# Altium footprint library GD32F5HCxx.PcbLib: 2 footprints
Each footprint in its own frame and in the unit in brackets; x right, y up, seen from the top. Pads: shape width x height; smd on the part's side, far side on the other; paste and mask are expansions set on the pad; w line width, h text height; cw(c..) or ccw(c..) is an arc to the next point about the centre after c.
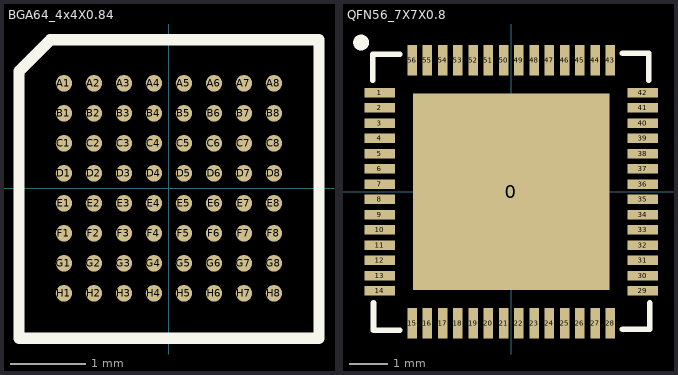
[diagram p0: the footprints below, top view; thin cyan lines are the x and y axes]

## BGA64_4x4X0.84 [mm]
pads (64):
  round 0.22 smd mask+0.05: A1(-1.4,1.4) A2(-1,1.4) A3(-0.6,1.4) A4(-0.2,1.4) A5(0.2,1.4) A6(0.6,1.4) A7(1,1.4) A8(1.4,1.4) B1(-1.4,1) B2(-1,1) B3(-0.6,1) B4(-0.2,1) B5(0.2,1) B6(0.6,1) B7(1,1) B8(1.4,1) C1(-1.4,0.6) C2(-1,0.6) C3(-0.6,0.6) C4(-0.2,0.6) C5(0.2,0.6) C6(0.6,0.6) C7(1,0.6) C8(1.4,0.6) D1(-1.4,0.2) D2(-1,0.2) D3(-0.6,0.2) D4(-0.2,0.2) D5(0.2,0.2) D6(0.6,0.2) D7(1,0.2) D8(1.4,0.2) E1(-1.4,-0.2) E2(-1,-0.2) E3(-0.6,-0.2) E4(-0.2,-0.2) E5(0.2,-0.2) E6(0.6,-0.2) E7(1,-0.2) E8(1.4,-0.2) F1(-1.4,-0.6) F2(-1,-0.6) F3(-0.6,-0.6) F4(-0.2,-0.6) F5(0.2,-0.6) F6(0.6,-0.6) F7(1,-0.6) F8(1.4,-0.6) G1(-1.4,-1) G2(-1,-1) G3(-0.6,-1) G4(-0.2,-1) G5(0.2,-1) G6(0.6,-1) G7(1,-1) G8(1.4,-1) H1(-1.4,-1.4) H2(-1,-1.4) H3(-0.6,-1.4) H4(-0.2,-1.4) H5(0.2,-1.4) H6(0.6,-1.4) H7(1,-1.4) H8(1.4,-1.4)
Top Overlay:
  lines w0.152: -2,-2 -2,1.562 -1.581,1.981 2,1.981 2,-2 -2,-2
3D body "BGA64C40P8X8_400X400X84.step": height 0.84, standoff 0, extent -2,-2 2,2

## QFN56_7X7X0.8 [mm]
pads (57):
  rect 5.15x5.15 smd: 0(0,0)
  rect 0.8x0.25 smd: 1(-3.45,2.6) 2(-3.45,2.2) 3(-3.45,1.8) 4(-3.45,1.4) 5(-3.45,1) 6(-3.45,0.6) 7(-3.45,0.2) 8(-3.45,-0.2) 9(-3.45,-0.6) 10(-3.45,-1) 11(-3.45,-1.4) 12(-3.45,-1.8) 13(-3.45,-2.2) 14(-3.45,-2.6) 29(3.45,-2.6) 30(3.45,-2.2) 31(3.45,-1.8) 32(3.45,-1.4) 33(3.45,-1) 34(3.45,-0.6) 35(3.45,-0.2) 36(3.45,0.2) 37(3.45,0.6) 38(3.45,1) 39(3.45,1.4) 40(3.45,1.8) 41(3.45,2.2) 42(3.45,2.6)
  rect 0.25x0.8 smd: 15(-2.6,-3.45) 16(-2.2,-3.45) 17(-1.8,-3.45) 18(-1.4,-3.45) 19(-1,-3.45) 20(-0.6,-3.45) 21(-0.2,-3.45) 22(0.2,-3.45) 23(0.6,-3.45) 24(1,-3.45) 25(1.4,-3.45) 26(1.8,-3.45) 27(2.2,-3.45) 28(2.6,-3.45) 43(2.6,3.45) 44(2.2,3.45) 45(1.8,3.45) 46(1.4,3.45) 47(1,3.45) 48(0.6,3.45) 49(0.2,3.45) 50(-0.2,3.45) 51(-0.6,3.45) 52(-1,3.45) 53(-1.4,3.45) 54(-1.8,3.45) 55(-2.2,3.45) 56(-2.6,3.45)
Top Overlay:
  circle w0.254: c-3.937,3.912 r0.08
  lines w0.152: -3.632,2.921 -3.632,3.607 -2.921,3.607 ; -3.607,-2.921 -3.607,-3.632 -2.921,-3.632 ; 2.921,-3.607 3.632,-3.607 3.632,-2.921 ; 2.921,3.632 3.607,3.632 3.607,2.921
3D body "QFN40P700X700X80_HS-57N.step": height 0.8, standoff 0, extent -3.551,-3.551 3.551,3.551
